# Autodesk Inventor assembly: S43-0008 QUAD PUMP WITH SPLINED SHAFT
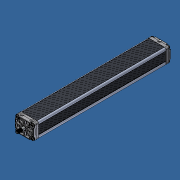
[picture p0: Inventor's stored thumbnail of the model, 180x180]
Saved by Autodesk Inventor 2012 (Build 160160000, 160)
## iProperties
Created: 2013-10
Part Number: S43-0008 QUAD PUMP WITH SPLINED SHAFT
Document SubType Name: Assembly
Designer: Admin
Author: Admin
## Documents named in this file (8)
- C:\Andys Backup Data\ANDY'S INVENTOR\INVENTOR LIBRARIES\PARTS LIBRARY\HYDRAULIC VERTICAL ADJUSTMENT\27.9001Telescoping Twin Leg System\SUBCOMPONENTS\Qxx18_crank pump\S43-0008 QUAD PUMP WITH SPLINED SHAFT.iam
- C:\Andys Backup Data\ANDY'S INVENTOR\INVENTOR LIBRARIES\PARTS LIBRARY\HYDRAULIC VERTICAL ADJUSTMENT\27.9001Telescoping Twin Leg System\SUBCOMPONENTS\Qxx18_crank pump\Quad Frontplate Assembly.iam
- C:\Andys Backup Data\ANDY'S INVENTOR\INVENTOR LIBRARIES\PARTS LIBRARY\HYDRAULIC VERTICAL ADJUSTMENT\27.9001Telescoping Twin Leg System\SUBCOMPONENTS\Qxx18_crank pump\Quad Connecting Plug_18mm.ipt
- C:\Andys Backup Data\ANDY'S INVENTOR\INVENTOR LIBRARIES\PARTS LIBRARY\HYDRAULIC VERTICAL ADJUSTMENT\27.9001Telescoping Twin Leg System\SUBCOMPONENTS\Qxx18_crank pump\662-00001 TRANSPORT SCREW.ipt
- C:\Andys Backup Data\ANDY'S INVENTOR\INVENTOR LIBRARIES\PARTS LIBRARY\HYDRAULIC VERTICAL ADJUSTMENT\27.9001Telescoping Twin Leg System\SUBCOMPONENTS\Qxx18_crank pump\668-01001 M5X30 TAPTITE TORX SCREW.ipt
- C:\Andys Backup Data\ANDY'S INVENTOR\INVENTOR LIBRARIES\PARTS LIBRARY\HYDRAULIC VERTICAL ADJUSTMENT\27.9001Telescoping Twin Leg System\SUBCOMPONENTS\Qxx18_crank pump\Splined_Shaft.ipt
- C:\Andys Backup Data\ANDY'S INVENTOR\INVENTOR LIBRARIES\PARTS LIBRARY\HYDRAULIC VERTICAL ADJUSTMENT\27.9001Telescoping Twin Leg System\SUBCOMPONENTS\Qxx18_crank pump\Quad Pump Housing_180 Stroke.ipt
- C:\Andys Backup Data\ANDY'S INVENTOR\INVENTOR LIBRARIES\PARTS LIBRARY\HYDRAULIC VERTICAL ADJUSTMENT\27.9001Telescoping Twin Leg System\SUBCOMPONENTS\Qxx18_crank pump\665-02102 Quad Endplate.ipt
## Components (20 placed, 7 different names)
1. Quad Frontplate Assembly:1 [sub-assembly]
2. Quad Connecting Plug_18mm:1
3. 662-00001 TRANSPORT SCREW:1
4. 662-00001 TRANSPORT SCREW:2
5. Quad Connecting Plug_18mm:2
6. 668-01001 M5X30 TAPTITE TORX SCREW:1
7. 668-01001 M5X30 TAPTITE TORX SCREW:2
8. Splined_Shaft:1
9. 668-01001 M5X30 TAPTITE TORX SCREW:3
10. 668-01001 M5X30 TAPTITE TORX SCREW:4
11. 668-01001 M5X30 TAPTITE TORX SCREW:5
12. 668-01001 M5X30 TAPTITE TORX SCREW:6
13. Quad Pump Housing_180 Stroke:1
14. 665-02102 Quad Endplate:1
15. 662-00001 TRANSPORT SCREW:3
16. 668-01001 M5X30 TAPTITE TORX SCREW:7
17. Quad Connecting Plug_18mm:3
18. Quad Connecting Plug_18mm:4
19. 668-01001 M5X30 TAPTITE TORX SCREW:8
20. 662-00001 TRANSPORT SCREW:4
